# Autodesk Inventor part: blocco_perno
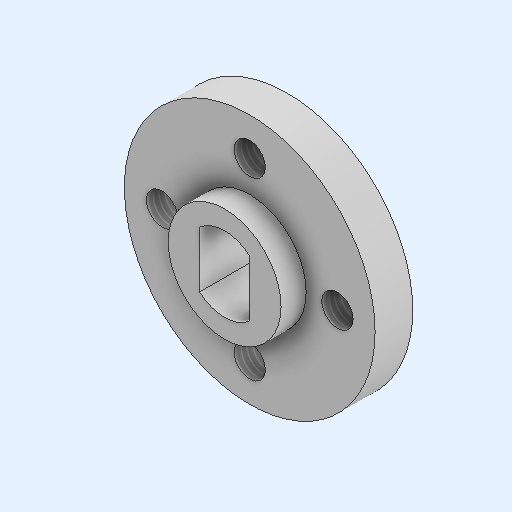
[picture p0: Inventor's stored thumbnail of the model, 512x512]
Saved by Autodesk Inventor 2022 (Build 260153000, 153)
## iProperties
Created: 2021-12
Part Number: blocco_perno
Material: Generico
Document SubType Name: Modeling
Designer: admin
Density: 1 g/cm^3
Appearance: Default
Author: admin
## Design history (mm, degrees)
sketch "Schizzo1"
  geometry: L1 (-2, -2.774)-(2, -2.774); L2 (2, -2.774)-(2, 2.774); L3 (2, 2.774)-(-2, 2.774); L4 (-2, 2.774)-(-2, -2.774); L5 (-2, -2.774)-(2, 2.774); L6 (2, -2.774)-(-2, 2.774); L7 (-4, -5)-(4, -5); L8 (4, -5)-(4, 5); L9 (4, 5)-(-4, 5); L10 (-4, 5)-(-4, -5); L11 (-4, -5)-(4, 5); L12 (4, -5)-(-4, 5); C1 r 3 at (0, 0); C2 r 10 at (0, 0); 5 further points
  constraints: 24 end point, 4 midpoint, 4 parallel, 2 centre point, 2 coincident, 2 horizontal, 2 perpendicular
  dimensions: "d0" = 6 diameter of C1; "d1" = 4 distance of L3.end L2.end; "d2" = 8 distance of L9.end L8.end; "d3" = 10 distance of L8.end L7.end; "d6" = 20 diameter of C2
extrude "Estrusione1" new body sketch "Schizzo1" distance "d4" = 5; taper "d5" = 0 deg
sketch "Schizzo3"
  geometry: C1 r 1.25 at (0, -7) reference; C2 r 1.25 at (7, 0) reference; C3 r 1.25 at (0, 7) reference; C4 r 1.25 at (-7, 0) reference; 1 further point
extrude "Estrusione2" cut sketch "Schizzo3" extent not by distance; stored distance "d7" = 0; taper "d8" = 0 deg
sketch "Schizzo4"
  geometry: C1 r 4.5 at (0, 0); C2 r 10 at (0, 0) reference; 1 further point
  constraints: 1 centre point, 1 coincident
  dimensions: "d9" = 9 diameter of C1
extrude "Estrusione3" cut sketch "Schizzo4" distance "d10" = 2; taper "d11" = 0 deg
feature "Filettatura1" dims "d12" = 15, "d13" = 0
feature "Filettatura2" dims "d14" = 15, "d15" = 0
feature "Filettatura3" dims "d16" = 15, "d17" = 0
feature "Filettatura4" dims "d18" = 15, "d19" = 0
node "Solido1"
node "Riferimento5"
node "Riferimento6"
node "Riferimento7"
node "Riferimento8"
